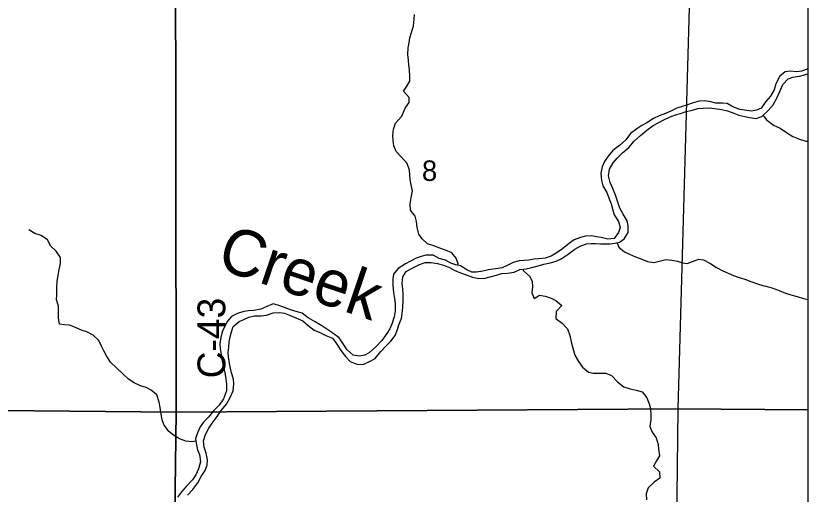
# Model space of a CAD drawing. Extents: x 1772825 to 1773716, y 1138558 to 1139032.
# Drawn here: x 1772831.349 to 1772832.158, y 1138560.049 to 1138560.538 of the extents above; entities that cross this region are included whole.
import ezdxf

# ---------------------------------------------------------------- set-up
doc = ezdxf.new("R2010")
doc.units = 0
for name, color, linetype in [('GM_X_County_Road_Text', 7, 'Continuous'), ('GM_X_Major_River', 7, 'Continuous'), ('GM_X_Major_River_Text', 7, 'Continuous'), ('GM_X_Minor_River', 7, 'Continuous'), ('GM_X_Section', 7, 'Continuous'), ('GM_X_Section_Text', 7, 'Continuous'), ('GM_X_Township', 7, 'Continuous')]:
    doc.layers.add(name, color=color, linetype=linetype)

msp = doc.modelspace()

# ---------------------------------------------------------------- linework, layer by layer
at = {"layer": 'GM_X_Major_River'}
for points in [[(1772832.15791, 1138560.48372), (1772832.15116, 1138560.48146), (1772832.14622, 1138560.48072), (1772832.13996, 1138560.48132), (1772832.13446, 1138560.48058), (1772832.12893, 1138560.47605), (1772832.12491, 1138560.46829), (1772832.12318, 1138560.46222), (1772832.11954, 1138560.45579), (1772832.11477, 1138560.45031), (1772832.11, 1138560.4435), (1772832.10506, 1138560.44143), (1772832.10012, 1138560.4405), (1772832.0931, 1138560.44129), (1772832.08817, 1138560.44226), (1772832.08116, 1138560.44476), (1772832.0751, 1138560.4482), (1772832.07036, 1138560.4486), (1772832.06352, 1138560.44863), (1772832.05859, 1138560.44998), (1772832.05196, 1138560.45114), (1772832.04683, 1138560.4506), (1772832.03942, 1138560.44873), (1772832.03391, 1138560.44667), (1772832.02916, 1138560.44517), (1772832.02402, 1138560.44348), (1772832.01927, 1138560.44104), (1772832.01223, 1138560.43803), (1772832.00596, 1138560.43578), (1772832.00006, 1138560.43296), (1772831.9934, 1138560.42863), (1772831.98808, 1138560.4258), (1772831.98294, 1138560.42222), (1772831.97646, 1138560.4175), (1772831.97169, 1138560.41107), (1772831.96521, 1138560.40522), (1772831.95874, 1138560.40012), (1772831.95378, 1138560.39445), (1772831.95015, 1138560.38916), (1772831.94766, 1138560.38366), (1772831.9463, 1138560.37722), (1772831.94684, 1138560.36963), (1772831.94833, 1138560.36412), (1772831.95248, 1138560.35727), (1772831.95492, 1138560.351), (1772831.95679, 1138560.34587), (1772831.95847, 1138560.33922), (1772831.95978, 1138560.33447), (1772831.9643, 1138560.32762), (1772831.96598, 1138560.32154), (1772831.96445, 1138560.31662), (1772831.96005, 1138560.31018), (1772831.95341, 1138560.30964), (1772831.94658, 1138560.31119), (1772831.94184, 1138560.31216), (1772831.9371, 1138560.31294), (1772831.93064, 1138560.31278), (1772831.92552, 1138560.31147), (1772831.91924, 1138560.30903), (1772831.91448, 1138560.30544), (1772831.90706, 1138560.29978), (1772831.90058, 1138560.29545), (1772831.89563, 1138560.29224), (1772831.88955, 1138560.29018), (1772831.8831, 1138560.28964), (1772831.87835, 1138560.28909), (1772831.87284, 1138560.28835), (1772831.8681, 1138560.288)], [(1772831.74458, 1138560.2538), (1772831.74422, 1138560.25854), (1772831.74368, 1138560.26424), (1772831.74409, 1138560.27126), (1772831.74772, 1138560.27674), (1772831.75381, 1138560.27994), (1772831.76122, 1138560.28371), (1772831.76693, 1138560.28577), (1772831.77319, 1138560.28574), (1772831.77964, 1138560.28477), (1772831.78665, 1138560.28265), (1772831.79177, 1138560.28054), (1772831.79669, 1138560.27805), (1772831.80313, 1138560.27518), (1772831.80995, 1138560.27287), (1772831.81526, 1138560.27095), (1772831.82, 1138560.26979), (1772831.82683, 1138560.26958), (1772831.83348, 1138560.27126), (1772831.83975, 1138560.27275), (1772831.84507, 1138560.27443), (1772831.85115, 1138560.27498), (1772831.8578, 1138560.27608), (1772831.8635, 1138560.27872), (1772831.87015, 1138560.27945), (1772831.87604, 1138560.28056), (1772831.88231, 1138560.28243), (1772831.88801, 1138560.28412), (1772831.89447, 1138560.28561), (1772831.90074, 1138560.28729), (1772831.90587, 1138560.28954), (1772831.91291, 1138560.29445), (1772831.91977, 1138560.29935), (1772831.9251, 1138560.30236), (1772831.93156, 1138560.3048), (1772831.93631, 1138560.30535), (1772831.94105, 1138560.30533), (1772831.94598, 1138560.30493), (1772831.95073, 1138560.30472), (1772831.95585, 1138560.30489), (1772831.9606, 1138560.30563), (1772831.96554, 1138560.30655), (1772831.9703, 1138560.31014), (1772831.97431, 1138560.31657), (1772831.97416, 1138560.32378), (1772831.97323, 1138560.32853), (1772831.96927, 1138560.33519), (1772831.96588, 1138560.34146), (1772831.96325, 1138560.34831), (1772831.96119, 1138560.35458), (1772831.95857, 1138560.36142), (1772831.95575, 1138560.36769), (1772831.95426, 1138560.37434), (1772831.95505, 1138560.38117), (1772831.95906, 1138560.3876), (1772831.96288, 1138560.39252), (1772831.96841, 1138560.398), (1772831.97488, 1138560.40347), (1772831.98041, 1138560.40971), (1772831.9867, 1138560.41556), (1772831.99337, 1138560.42104), (1772831.99965, 1138560.42594), (1772832.00479, 1138560.42839), (1772832.0105, 1138560.43159), (1772832.01715, 1138560.4346), (1772832.02267, 1138560.43666), (1772832.02761, 1138560.43816), (1772832.03331, 1138560.44003), (1772832.03996, 1138560.44152), (1772832.04547, 1138560.44301), (1772832.0506, 1138560.44356), (1772832.05686, 1138560.44372), (1772832.06502, 1138560.44274), (1772832.06976, 1138560.44215), (1772832.07564, 1138560.4408), (1772832.08189, 1138560.43849), (1772832.087, 1138560.43639), (1772832.09345, 1138560.43484), (1772832.09819, 1138560.43406), (1772832.10483, 1138560.43289), (1772832.11072, 1138560.43496), (1772832.1172, 1138560.441), (1772832.12216, 1138560.44705), (1772832.12599, 1138560.45367), (1772832.12905, 1138560.46049), (1772832.13212, 1138560.4675), (1772832.13746, 1138560.47336), (1772832.14221, 1138560.47504), (1772832.14924, 1138560.47615), (1772832.15418, 1138560.47765), (1772832.15791, 1138560.47865)], [(1772831.8681, 1138560.288), (1772831.86297, 1138560.28764), (1772831.85689, 1138560.28596), (1772831.85194, 1138560.28332), (1772831.84567, 1138560.2805), (1772831.83883, 1138560.2792), (1772831.8318, 1138560.27828), (1772831.82591, 1138560.27698), (1772831.81946, 1138560.27606), (1772831.81452, 1138560.27608), (1772831.8096, 1138560.27838), (1772831.80316, 1138560.28239), (1772831.79842, 1138560.28355), (1772831.79312, 1138560.28509), (1772831.78763, 1138560.28834), (1772831.78118, 1138560.28988), (1772831.77512, 1138560.29332), (1772831.76772, 1138560.29336), (1772831.76297, 1138560.29186), (1772831.75803, 1138560.29017), (1772831.75194, 1138560.28716), (1772831.74699, 1138560.28434), (1772831.73957, 1138560.27981), (1772831.73461, 1138560.27395), (1772831.73421, 1138560.26921), (1772831.73418, 1138560.26257), (1772831.73472, 1138560.25517), (1772831.73583, 1138560.2489), (1772831.73638, 1138560.24397), (1772831.73654, 1138560.23638), (1772831.73556, 1138560.23031), (1772831.73326, 1138560.22387), (1772831.73095, 1138560.21819), (1772831.72809, 1138560.21326), (1772831.72293, 1138560.20627), (1772831.71683, 1138560.19965), (1772831.71035, 1138560.1938), (1772831.70541, 1138560.19116), (1772831.70009, 1138560.19023), (1772831.69345, 1138560.19102), (1772831.6874, 1138560.19655), (1772831.68325, 1138560.20283), (1772831.67929, 1138560.20873), (1772831.67267, 1138560.2135), (1772831.66775, 1138560.21694), (1772831.66169, 1138560.22114), (1772831.65469, 1138560.22515), (1772831.64768, 1138560.22936), (1772831.64144, 1138560.23394), (1772831.63632, 1138560.23547), (1772831.62969, 1138560.23759), (1772831.62363, 1138560.2397), (1772831.6168, 1138560.2422), (1772831.61206, 1138560.24374), (1772831.60541, 1138560.24092), (1772831.59932, 1138560.23829), (1772831.59211, 1138560.23661), (1772831.5866, 1138560.23645), (1772831.58185, 1138560.2359), (1772831.57539, 1138560.23365), (1772831.56949, 1138560.23064), (1772831.5653, 1138560.22572), (1772831.56262, 1138560.2208), (1772831.56032, 1138560.2155), (1772831.55839, 1138560.20943), (1772831.55742, 1138560.2028), (1772831.55797, 1138560.19786), (1772831.5587, 1138560.19179), (1772831.55944, 1138560.18685), (1772831.56093, 1138560.1802), (1772831.5626, 1138560.17336), (1772831.56372, 1138560.1671), (1772831.56426, 1138560.16121), (1772831.56423, 1138560.15457), (1772831.56116, 1138560.14662), (1772831.55677, 1138560.14018), (1772831.55105, 1138560.13433), (1772831.54589, 1138560.1279), (1772831.54075, 1138560.12279), (1772831.5375, 1138560.11788), (1772831.53482, 1138560.11181), (1772831.53271, 1138560.10613), (1772831.53325, 1138560.1012), (1772831.53474, 1138560.09436), (1772831.53662, 1138560.08961), (1772831.53773, 1138560.0822), (1772831.53561, 1138560.075), (1772831.53293, 1138560.06875), (1772831.52949, 1138560.06383), (1772831.5232, 1138560.05703), (1772831.51824, 1138560.05136), (1772831.51442, 1138560.04606)], [(1772831.52449, 1138560.0481), (1772831.53001, 1138560.05396), (1772831.53498, 1138560.06058), (1772831.53861, 1138560.06702), (1772831.54243, 1138560.07345), (1772831.54455, 1138560.07914), (1772831.54476, 1138560.08407), (1772831.54365, 1138560.0909), (1772831.54159, 1138560.09718), (1772831.54086, 1138560.10363), (1772831.54278, 1138560.11007), (1772831.54642, 1138560.1167), (1772831.54966, 1138560.12162), (1772831.55463, 1138560.12862), (1772831.55883, 1138560.13467), (1772831.56417, 1138560.1411), (1772831.56819, 1138560.14772), (1772831.57106, 1138560.15454), (1772831.57166, 1138560.16194), (1772831.5715, 1138560.16669), (1772831.56943, 1138560.17295), (1772831.56832, 1138560.1777), (1772831.5672, 1138560.18264), (1772831.56647, 1138560.18929), (1772831.56611, 1138560.19403), (1772831.5667, 1138560.19915), (1772831.56711, 1138560.20465), (1772831.56789, 1138560.20996), (1772831.56924, 1138560.21489), (1772831.57116, 1138560.22057), (1772831.57706, 1138560.22567), (1772831.58182, 1138560.22774), (1772831.58695, 1138560.22999), (1772831.59303, 1138560.2313), (1772831.59968, 1138560.23146), (1772831.60518, 1138560.232), (1772831.61202, 1138560.23425), (1772831.61867, 1138560.2346), (1772831.62341, 1138560.23401), (1772831.62853, 1138560.2319), (1772831.63497, 1138560.22922), (1772831.64236, 1138560.22634), (1772831.64765, 1138560.22139), (1772831.65389, 1138560.21681), (1772831.65938, 1138560.21413), (1772831.66582, 1138560.21125), (1772831.67246, 1138560.20838), (1772831.67698, 1138560.20229), (1772831.68094, 1138560.19601), (1772831.68604, 1138560.18953), (1772831.69038, 1138560.18477), (1772831.6972, 1138560.1819), (1772831.70384, 1138560.18149), (1772831.71107, 1138560.18487), (1772831.71602, 1138560.18789), (1772831.72174, 1138560.19489), (1772831.72708, 1138560.20056), (1772831.73185, 1138560.20528), (1772831.73643, 1138560.21114), (1772831.73873, 1138560.2172), (1772831.74027, 1138560.22213), (1772831.74277, 1138560.22857), (1772831.74374, 1138560.23331), (1772831.74414, 1138560.24014), (1772831.74456, 1138560.24735), (1772831.74458, 1138560.2538)]]:
    msp.add_lwpolyline(points, dxfattribs=at)
at = {"layer": 'GM_X_Minor_River'}
for points in [[(1772831.80036, 1138560.28308), (1772831.8007, 1138560.2843), (1772831.79864, 1138560.29019), (1772831.79411, 1138560.29571), (1772831.78786, 1138560.29858), (1772831.78198, 1138560.30051), (1772831.77592, 1138560.303), (1772831.76929, 1138560.30492), (1772831.764, 1138560.30988), (1772831.7606, 1138560.31464), (1772831.75892, 1138560.32147), (1772831.75819, 1138560.32774), (1772831.75689, 1138560.33325), (1772831.75198, 1138560.33915), (1772831.75162, 1138560.3456), (1772831.7526, 1138560.35186), (1772831.75415, 1138560.35887), (1772831.75266, 1138560.36533), (1772831.75173, 1138560.37065), (1772831.75102, 1138560.38014), (1772831.74877, 1138560.38698), (1772831.74291, 1138560.39326), (1772831.73743, 1138560.39917), (1772831.73499, 1138560.40487), (1772831.73426, 1138560.41038), (1772831.7339, 1138560.41531), (1772831.73469, 1138560.42214), (1772831.7368, 1138560.42801), (1772831.7431, 1138560.43538), (1772831.74674, 1138560.44334), (1772831.75075, 1138560.4492), (1772831.75077, 1138560.45433), (1772831.74491, 1138560.46099), (1772831.74835, 1138560.46591), (1772831.75141, 1138560.47121), (1772831.75143, 1138560.47595), (1772831.75089, 1138560.4826), (1772831.75054, 1138560.48791), (1772831.74999, 1138560.49266), (1772831.74944, 1138560.49816), (1772831.74985, 1138560.50518), (1772831.75063, 1138560.51049), (1772831.75141, 1138560.51523), (1772831.75296, 1138560.52091), (1772831.75507, 1138560.52774), (1772831.75586, 1138560.53437), (1772831.75607, 1138560.53911)], [(1772832.11192, 1138560.43607), (1772832.11526, 1138560.43171), (1772832.12245, 1138560.42618), (1772832.12927, 1138560.42311), (1772832.1357, 1138560.41853), (1772832.14214, 1138560.41471), (1772832.14896, 1138560.41184), (1772832.1554, 1138560.40972), (1772832.15791, 1138560.40971)], [(1772831.53304, 1138560.10316), (1772831.5289, 1138560.10273), (1772831.52263, 1138560.10314), (1772831.51619, 1138560.10582), (1772831.51032, 1138560.10926), (1772831.50541, 1138560.11327), (1772831.50031, 1138560.12031), (1772831.49863, 1138560.12506), (1772831.49733, 1138560.13304), (1772831.49659, 1138560.13778), (1772831.49567, 1138560.1431), (1772831.49323, 1138560.1507), (1772831.48737, 1138560.15547), (1772831.48244, 1138560.15796), (1772831.47638, 1138560.15988), (1772831.47013, 1138560.16275), (1772831.46426, 1138560.16676), (1772831.4584, 1138560.1721), (1772831.44593, 1138560.18392), (1772831.44178, 1138560.19058), (1772831.43914, 1138560.19571), (1772831.4367, 1138560.20047), (1772831.43388, 1138560.20617), (1772831.42821, 1138560.2117), (1772831.42177, 1138560.21514), (1772831.41684, 1138560.2163), (1772831.41021, 1138560.21936), (1772831.40415, 1138560.22186), (1772831.39902, 1138560.22207), (1772831.3939, 1138560.22285), (1772831.39279, 1138560.2293), (1772831.393, 1138560.23462), (1772831.39284, 1138560.24107), (1772831.39097, 1138560.24753), (1772831.39099, 1138560.25303), (1772831.39121, 1138560.25986), (1772831.39162, 1138560.26688), (1772831.3926, 1138560.27238), (1772831.39357, 1138560.27863), (1772831.39493, 1138560.2847), (1772831.39477, 1138560.29096), (1772831.39062, 1138560.29724), (1772831.38495, 1138560.30258), (1772831.38156, 1138560.30885), (1772831.37512, 1138560.31344), (1772831.36868, 1138560.31555), (1772831.36243, 1138560.31918)], [(1772831.96292, 1138560.30606), (1772831.96476, 1138560.30162), (1772831.97062, 1138560.29667), (1772831.97555, 1138560.29437), (1772831.9818, 1138560.2915), (1772831.98805, 1138560.28919), (1772831.99411, 1138560.28689), (1772832.00037, 1138560.28592), (1772832.00588, 1138560.28703), (1772832.01272, 1138560.2889), (1772832.01879, 1138560.28811), (1772832.02448, 1138560.28714), (1772832.02979, 1138560.28541), (1772832.03453, 1138560.28482), (1772832.03985, 1138560.2867), (1772832.0465, 1138560.28932), (1772832.05125, 1138560.28854), (1772832.0575, 1138560.28529), (1772832.06431, 1138560.28071), (1772832.07094, 1138560.27746), (1772832.07624, 1138560.27478), (1772832.08173, 1138560.27248), (1772832.08647, 1138560.27075), (1772832.09329, 1138560.26863), (1772832.09955, 1138560.26652), (1772832.10637, 1138560.26402), (1772832.11149, 1138560.26248), (1772832.11623, 1138560.26114), (1772832.12097, 1138560.25998), (1772832.12817, 1138560.25729), (1772832.1348, 1138560.25461), (1772832.14029, 1138560.25288), (1772832.14655, 1138560.25114), (1772832.15318, 1138560.24903), (1772832.15791, 1138560.24806)], [(1772831.86689, 1138560.27909), (1772831.86729, 1138560.27718), (1772831.87353, 1138560.27184), (1772831.87617, 1138560.2669), (1772831.87671, 1138560.26102), (1772831.87592, 1138560.25495), (1772831.87818, 1138560.24906), (1772831.88369, 1138560.25245), (1772831.88938, 1138560.25129), (1772831.89564, 1138560.24936), (1772831.90056, 1138560.24687), (1772831.90642, 1138560.24192), (1772831.9007, 1138560.23568), (1772831.90029, 1138560.22866), (1772831.90691, 1138560.2237), (1772831.9122, 1138560.21798), (1772831.91483, 1138560.21133), (1772831.91594, 1138560.20487), (1772831.91762, 1138560.19842), (1772831.91968, 1138560.1912), (1772831.92345, 1138560.18473), (1772831.9276, 1138560.17902), (1772831.93384, 1138560.17387), (1772831.93858, 1138560.1729), (1772831.94484, 1138560.17269), (1772831.95129, 1138560.17266), (1772831.95717, 1138560.17036), (1772831.96321, 1138560.16388), (1772831.96983, 1138560.15892), (1772831.97628, 1138560.1568), (1772831.98234, 1138560.15545), (1772831.98841, 1138560.15353), (1772831.99332, 1138560.14762), (1772831.99576, 1138560.14135), (1772831.99707, 1138560.1366), (1772831.99723, 1138560.13015), (1772831.99721, 1138560.12522), (1772831.99642, 1138560.1182), (1772831.99867, 1138560.1125), (1772832.00282, 1138560.1066), (1772832.00469, 1138560.09995), (1772832.00524, 1138560.09501), (1772832.00635, 1138560.08818), (1772832.00329, 1138560.08326), (1772832.00023, 1138560.07758), (1772832.00628, 1138560.07186), (1772832.00644, 1138560.06541), (1772832.00073, 1138560.06126), (1772831.99463, 1138560.05559), (1772831.99271, 1138560.04952), (1772831.99287, 1138560.04345)]]:
    msp.add_lwpolyline(points, dxfattribs=at)
at = {"layer": 'GM_X_Section'}
for p, q in [((1772832.15791, 1138560.13524), (1772832.15791, 1138560.63153)), ((1772832.15791, 1138559.63216), (1772832.15791, 1138560.13524))]:
    msp.add_line(p, q, dxfattribs=at)
for points in [[(1772831.00818, 1138560.6381), (1772831.51219, 1138560.63952), (1772831.51303, 1138560.13287), (1772831.0066, 1138560.13752)], [(1772831.51219, 1138560.63952), (1772832.03869, 1138560.63114), (1772832.02482, 1138560.13632), (1772831.51303, 1138560.13287)], [(1772831.0066, 1138560.13752), (1772831.51303, 1138560.13287), (1772831.50632, 1138559.63232), (1772830.99854, 1138559.63168), (1772831.00637, 1138560.13184)], [(1772831.51303, 1138560.13287), (1772832.02482, 1138560.13632), (1772832.01904, 1138559.63292), (1772831.50632, 1138559.63232)]]:
    msp.add_lwpolyline(points, close=True, dxfattribs=at)
for points in [[(1772832.15791, 1138560.63153), (1772832.03869, 1138560.63114), (1772832.02482, 1138560.13632), (1772832.15791, 1138560.13524)], [(1772832.15791, 1138560.13524), (1772832.02482, 1138560.13632), (1772832.01904, 1138559.63292), (1772832.15791, 1138559.63216)]]:
    msp.add_lwpolyline(points, dxfattribs=at)
at = {"layer": 'GM_X_Township'}
msp.add_line((1772832.15791, 1138558.11883), (1772832.15791, 1138561.13315), dxfattribs=at)

# ---------------------------------------------------------------- texts
at = {"layer": 'GM_X_County_Road_Text'}
msp.add_text('C-43', height=0.028409, rotation=90, dxfattribs=at).set_placement((1772831.5631, 1138560.16746))
at = {"layer": 'GM_X_Major_River_Text'}
msp.add_text('Creek', height=0.047366, rotation=341.27206, dxfattribs=at).set_placement((1772831.55267, 1138560.28049))
at = {"layer": 'GM_X_Section_Text'}
msp.add_text('8', height=0.02093, rotation=0.00001, dxfattribs=at).set_placement((1772831.76374, 1138560.36916))

doc.saveas('drawing.dxf')
